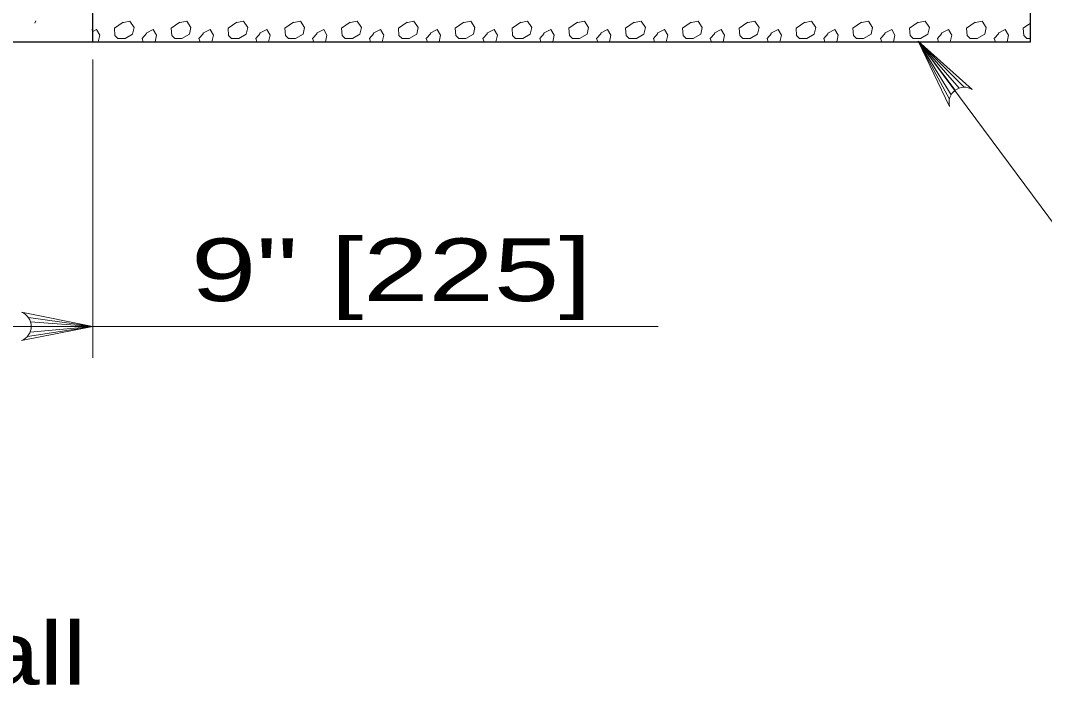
# Model space of a CAD drawing. Extents: x 685.4 to 719.4, y 1059.8 to 1105.8.
# Drawn here: x 707.476 to 710.022, y 1088.265 to 1089.92 of the extents above; entities that cross this region are included whole.
import ezdxf
from ezdxf.enums import TextEntityAlignment as Align

# ---------------------------------------------------------------- set-up
doc = ezdxf.new("R2010")
doc.units = 0
doc.header["$LTSCALE"] = 0.062
doc.layers.add('1', color=7, linetype='Continuous', lineweight=13)

msp = doc.modelspace()

# ---------------------------------------------------------------- linework, layer by layer
at = {"layer": '1', "lineweight": 25}
for p, q in [((707.65533, 1089.867), (707.65533, 1091.15183)), ((709.98792, 1089.867), (709.98792, 1091.15183)), ((707.25, 1089.867), (707.65533, 1089.867)), ((707.65533, 1089.867), (709.98792, 1089.867))]:
    msp.add_line(p, q, dxfattribs=at)
at = {"layer": '1'}
for p, q in [((707.51125, 1089.9135), (707.51358, 1089.91892)), ((707.65375, 1089.8985), (707.65433, 1089.89317)), ((709.80025, 1089.74642), (709.7085, 1089.869)), ((709.79042, 1089.7355), (709.7085, 1089.869)), ((709.78575, 1089.72433), (709.7085, 1089.869)), ((709.81033, 1089.75183), (709.7085, 1089.869)), ((709.82242, 1089.75417), (709.7085, 1089.869)), ((707.65533, 1089.82275), (707.65533, 1089.08033)), ((707.25, 1089.159), (709.06117, 1089.159)), ((707.49317, 1089.13417), (707.65533, 1089.159)), ((707.49508, 1089.18142), (707.65533, 1089.159)), ((707.49933, 1089.14458), (707.65533, 1089.159)), ((707.5005, 1089.17033), (707.65533, 1089.159)), ((707.50217, 1089.159), (707.65533, 1089.159))]:
    msp.add_line(p, q, dxfattribs=at)
for points in [[(707.66892, 1089.867), (707.67258, 1089.88342), (707.66442, 1089.8975), (707.65533, 1089.893)], [(707.73067, 1089.91592), (707.709, 1089.901), (707.7105, 1089.88317), (707.718, 1089.87567), (707.73592, 1089.87567), (707.7545, 1089.88617), (707.75825, 1089.90258), (707.74783, 1089.91817), (707.73142, 1089.91517)], [(707.81025, 1089.867), (707.81392, 1089.88342), (707.80575, 1089.8975), (707.78783, 1089.88867)], [(707.87192, 1089.91592), (707.85033, 1089.901), (707.85183, 1089.88317), (707.85925, 1089.87567), (707.87717, 1089.87567), (707.89583, 1089.88617), (707.89958, 1089.90258), (707.88908, 1089.91817), (707.87267, 1089.91517)], [(707.9515, 1089.867), (707.95525, 1089.88342), (707.947, 1089.8975), (707.92908, 1089.88867)], [(708.01325, 1089.91592), (707.99167, 1089.901), (707.99317, 1089.88317), (708.00058, 1089.87567), (708.01842, 1089.87567), (708.03708, 1089.88617), (708.04083, 1089.90258), (708.03033, 1089.91817), (708.014, 1089.91517)], [(708.09275, 1089.867), (708.0965, 1089.88342), (708.08825, 1089.8975), (708.07033, 1089.88867)], [(708.15458, 1089.91592), (708.13292, 1089.901), (708.13442, 1089.88317), (708.14192, 1089.87567), (708.15975, 1089.87567), (708.17842, 1089.88617), (708.18217, 1089.90258), (708.17175, 1089.91817), (708.15533, 1089.91517)], [(708.234, 1089.867), (708.23775, 1089.88342), (708.22958, 1089.8975), (708.21167, 1089.88867)], [(708.29583, 1089.91592), (708.27417, 1089.901), (708.27567, 1089.88317), (708.28317, 1089.87567), (708.301, 1089.87567), (708.31967, 1089.88617), (708.32342, 1089.90258), (708.313, 1089.91817), (708.29658, 1089.91517)], [(708.37525, 1089.867), (708.379, 1089.88342), (708.37083, 1089.8975), (708.353, 1089.88867)], [(708.43708, 1089.91592), (708.41542, 1089.901), (708.41692, 1089.88317), (708.42442, 1089.87567), (708.44233, 1089.87567), (708.46092, 1089.88617), (708.46467, 1089.90258), (708.45425, 1089.91817), (708.43783, 1089.91517)], [(708.51667, 1089.867), (708.52033, 1089.88342), (708.51217, 1089.8975), (708.49425, 1089.88867)], [(708.57833, 1089.91592), (708.55667, 1089.901), (708.55817, 1089.88317), (708.56567, 1089.87567), (708.58358, 1089.87567), (708.60217, 1089.88617), (708.60592, 1089.90258), (708.5955, 1089.91817), (708.57908, 1089.91517)], [(708.65792, 1089.867), (708.66158, 1089.88342), (708.65342, 1089.8975), (708.6355, 1089.88867)], [(708.71967, 1089.91592), (708.69808, 1089.901), (708.69958, 1089.88317), (708.707, 1089.87567), (708.72483, 1089.87567), (708.7435, 1089.88617), (708.74725, 1089.90258), (708.73675, 1089.91817), (708.72042, 1089.91517)], [(708.79917, 1089.867), (708.80292, 1089.88342), (708.79467, 1089.8975), (708.77675, 1089.88867)], [(708.86092, 1089.91592), (708.83933, 1089.901), (708.84083, 1089.88317), (708.84825, 1089.87567), (708.86617, 1089.87567), (708.88483, 1089.88617), (708.88858, 1089.90258), (708.87808, 1089.91817), (708.86167, 1089.91517)], [(708.94042, 1089.867), (708.94417, 1089.88342), (708.93592, 1089.8975), (708.918, 1089.88867)], [(709.00225, 1089.91592), (708.98058, 1089.901), (708.98208, 1089.88317), (708.98958, 1089.87567), (709.00742, 1089.87567), (709.02608, 1089.88617), (709.02983, 1089.90258), (709.01942, 1089.91817), (709.003, 1089.91517)], [(709.08167, 1089.867), (709.08542, 1089.88342), (709.07733, 1089.8975), (709.05942, 1089.88867)], [(709.1435, 1089.91592), (709.12183, 1089.901), (709.12333, 1089.88317), (709.13083, 1089.87567), (709.14867, 1089.87567), (709.16733, 1089.88617), (709.17108, 1089.90258), (709.16067, 1089.91817), (709.14425, 1089.91517)], [(709.223, 1089.867), (709.22675, 1089.88342), (709.21858, 1089.8975), (709.20067, 1089.88867)], [(709.28475, 1089.91592), (709.26308, 1089.901), (709.26458, 1089.88317), (709.27208, 1089.87567), (709.29, 1089.87567), (709.30858, 1089.88617), (709.31233, 1089.90258), (709.30192, 1089.91817), (709.2855, 1089.91517)], [(709.36433, 1089.867), (709.368, 1089.88342), (709.35983, 1089.8975), (709.34192, 1089.88867)], [(709.42608, 1089.91592), (709.40442, 1089.901), (709.40592, 1089.88317), (709.41342, 1089.87567), (709.43133, 1089.87567), (709.44983, 1089.88617), (709.45358, 1089.90258), (709.44317, 1089.91817), (709.42683, 1089.91517)], [(709.50558, 1089.867), (709.50925, 1089.88342), (709.50108, 1089.8975), (709.48317, 1089.88867)], [(709.56733, 1089.91592), (709.54575, 1089.901), (709.54725, 1089.88317), (709.55467, 1089.87567), (709.57258, 1089.87567), (709.59125, 1089.88617), (709.595, 1089.90258), (709.5845, 1089.91817), (709.56808, 1089.91517)], [(709.64683, 1089.867), (709.6505, 1089.88342), (709.64233, 1089.8975), (709.62442, 1089.88867)], [(709.70858, 1089.91592), (709.687, 1089.901), (709.6885, 1089.88317), (709.69592, 1089.87567), (709.71383, 1089.87567), (709.7325, 1089.88617), (709.73625, 1089.90258), (709.72575, 1089.91817), (709.70933, 1089.91517)], [(709.78817, 1089.867), (709.79183, 1089.88342), (709.78367, 1089.8975), (709.76575, 1089.88867)], [(709.84992, 1089.91592), (709.82825, 1089.901), (709.82975, 1089.88317), (709.83725, 1089.87567), (709.85508, 1089.87567), (709.87375, 1089.88617), (709.8775, 1089.90258), (709.86708, 1089.91817), (709.85067, 1089.91517)], [(709.92942, 1089.867), (709.93317, 1089.88342), (709.92492, 1089.8975), (709.90708, 1089.88867)], [(709.98492, 1089.91158), (709.9695, 1089.901), (709.971, 1089.88317), (709.9785, 1089.87567), (709.98492, 1089.87567)], [(707.78933, 1089.88792), (707.77817, 1089.87525), (707.781, 1089.867)], [(707.93058, 1089.88792), (707.91942, 1089.87525), (707.92233, 1089.867)], [(708.07183, 1089.88792), (708.06067, 1089.87525), (708.06358, 1089.867)], [(708.21317, 1089.88792), (708.20192, 1089.87525), (708.20483, 1089.867)], [(708.3545, 1089.88792), (708.34325, 1089.87525), (708.34617, 1089.867)], [(708.49575, 1089.88792), (708.48458, 1089.87525), (708.48742, 1089.867)], [(708.637, 1089.88792), (708.62583, 1089.87525), (708.62867, 1089.867)], [(708.77825, 1089.88792), (708.76708, 1089.87525), (708.77, 1089.867)], [(708.9195, 1089.88792), (708.90833, 1089.87525), (708.91125, 1089.867)], [(709.06092, 1089.88792), (709.04967, 1089.87525), (709.05258, 1089.867)], [(709.20217, 1089.88792), (709.19092, 1089.87525), (709.19383, 1089.867)], [(709.34342, 1089.88792), (709.33225, 1089.87525), (709.33508, 1089.867)], [(709.48467, 1089.88792), (709.4735, 1089.87525), (709.47633, 1089.867)], [(709.62592, 1089.88792), (709.61475, 1089.87525), (709.61767, 1089.867)], [(709.76725, 1089.88792), (709.75608, 1089.87525), (709.759, 1089.867)], [(709.90858, 1089.88792), (709.89733, 1089.87525), (709.90025, 1089.867)], [(709.78617, 1089.70608), (709.7085, 1089.869), (709.84283, 1089.7485)], [(709.7085, 1089.869), (710.21758, 1089.18283), (710.43367, 1089.18283)], [(707.47833, 1089.12358), (707.65533, 1089.159), (707.47833, 1089.19442)]]:
    msp.add_lwpolyline(points, dxfattribs=at)
for centre, start, end in [((709.82312, 1089.71587), 58.89731, 194.72344), ((707.464, 1089.15902), 292.08605, 67.91218)]:
    msp.add_arc(centre, 0.0382, start, end, dxfattribs=at)

# ---------------------------------------------------------------- texts
for s, width, p in [('9" [225]', 1.4, (708.39804, 1089.22192)), ('Cutoff Wall', 1.25, (707.00162, 1088.2675))]:
    msp.add_text(s, height=0.156, dxfattribs=dict(at, width=width)).set_placement(p, align=Align.CENTER)

doc.saveas('drawing.dxf')
